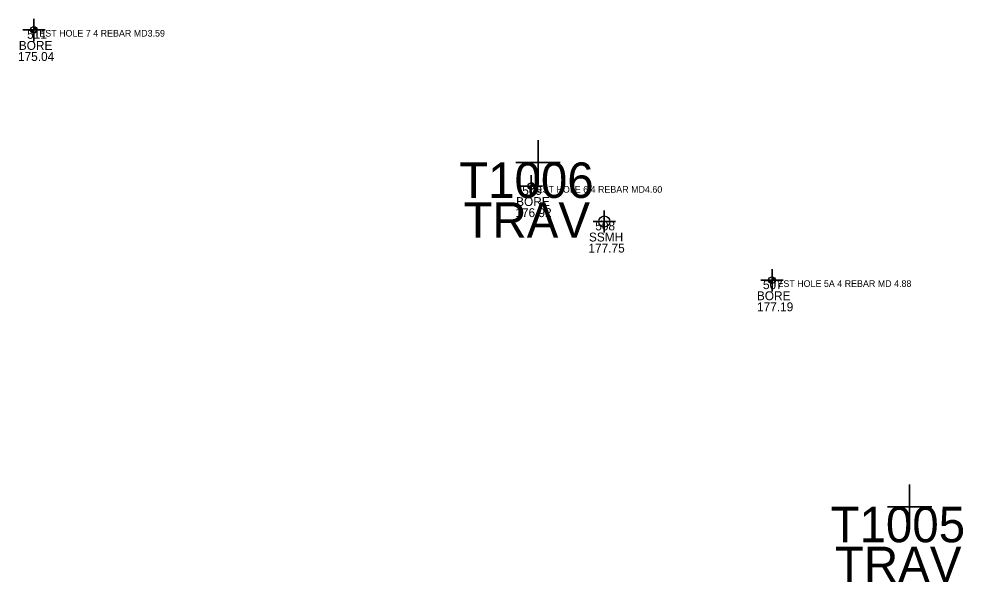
# Model space of a CAD drawing. Extents: x 1969314 to 1970910, y 795817 to 797766.
# Drawn here: x 1969314.1 to 1969527.1, y 797638.9 to 797766 of the extents above; entities that cross this region are included whole.
import ezdxf

# ---------------------------------------------------------------- set-up
doc = ezdxf.new("R2010")
doc.units = 0
for name, color, linetype in [('Level 63', 7, 'Continuous'), ('SV_Control_Boring', 7, 'Continuous'), ('SV_Control_Boring_Code', 7, 'Continuous'), ('SV_Control_Boring_Elev', 7, 'Continuous'), ('SV_Control_Boring_Name', 7, 'Continuous'), ('SV_Control_Boring_Shot', 7, 'Continuous'), ('SV_Control_CP_Code', 7, 'Continuous'), ('SV_Control_CP_Name', 7, 'Continuous'), ('SV_Control_CP_Shot', 7, 'Continuous'), ('SV_SS_Appurt_Code', 7, 'Continuous'), ('SV_SS_Appurt_Elev', 7, 'Continuous'), ('SV_SS_Appurt_name', 7, 'Continuous'), ('SV_SS_Appurtenances', 7, 'Continuous'), ('SV_SS_Appurtenances_Shots', 7, 'Continuous')]:
    doc.layers.add(name, color=color, linetype=linetype)

msp = doc.modelspace()

# ---------------------------------------------------------------- linework, layer by layer
at = {"layer": 'SV_Control_Boring'}
for p, q in [((1969316.79, 797763.55), (1969318.29, 797763.55)), ((1969317.54, 797762.8), (1969317.54, 797764.3)), ((1969429.7, 797727.55), (1969429.7, 797729.05)), ((1969428.95, 797728.3), (1969430.45, 797728.3)), ((1969483.99, 797706.29), (1969483.99, 797707.79)), ((1969483.24, 797707.04), (1969484.74, 797707.04))]:
    msp.add_line(p, q, dxfattribs=at)
for centre in [(1969317.54, 797763.55), (1969429.7, 797728.3), (1969483.99, 797707.04)]:
    msp.add_circle(centre, 0.75, dxfattribs=at)
for centre, radius, start, end in [((1969317.54, 797763.55), 0.698, 179.9999, 270.0002), ((1969317.54, 797763.55), 0.635, 179.9999, 270.0002), ((1969317.54, 797763.55), 0.573, 179.9999, 270.0002), ((1969317.54, 797763.55), 0.51, 179.9999, 270.0002), ((1969317.54, 797763.55), 0.448, 179.9999, 270.0002), ((1969317.54, 797763.55), 0.385, 179.9999, 270.0002), ((1969317.54, 797763.55), 0.693, 0.0001, 89.9995), ((1969317.54, 797763.55), 0.631, 0.0001, 89.9995), ((1969317.54, 797763.55), 0.569, 0.0001, 89.9995), ((1969317.54, 797763.55), 0.507, 0.0001, 89.9995), ((1969317.54, 797763.55), 0.445, 0.0001, 89.9995), ((1969317.54, 797763.55), 0.384, 0.0001, 89.9995), ((1969317.54, 797763.55), 0.322, 0.0001, 89.9995), ((1969429.7, 797728.3), 0.693, 0.0001, 89.9995), ((1969429.7, 797728.3), 0.631, 0.0001, 89.9995), ((1969429.7, 797728.3), 0.569, 0.0001, 89.9995), ((1969429.7, 797728.3), 0.507, 0.0001, 89.9995), ((1969429.7, 797728.3), 0.445, 0.0001, 89.9995), ((1969429.7, 797728.3), 0.384, 0.0001, 89.9995), ((1969429.7, 797728.3), 0.322, 0.0001, 89.9995), ((1969429.7, 797728.3), 0.698, 179.9999, 270.0002), ((1969429.7, 797728.3), 0.635, 179.9999, 270.0002), ((1969429.7, 797728.3), 0.573, 179.9999, 270.0002), ((1969429.7, 797728.3), 0.51, 179.9999, 270.0002), ((1969429.7, 797728.3), 0.448, 179.9999, 270.0002), ((1969429.7, 797728.3), 0.385, 179.9999, 270.0002), ((1969483.99, 797707.04), 0.693, 0.0001, 89.9995), ((1969483.99, 797707.04), 0.631, 0.0001, 89.9995), ((1969483.99, 797707.04), 0.569, 0.0001, 89.9995), ((1969483.99, 797707.04), 0.507, 0.0001, 89.9995), ((1969483.99, 797707.04), 0.445, 0.0001, 89.9995), ((1969483.99, 797707.04), 0.384, 0.0001, 89.9995), ((1969483.99, 797707.04), 0.322, 0.0001, 89.9995), ((1969483.99, 797707.04), 0.698, 179.9999, 270.0002), ((1969483.99, 797707.04), 0.635, 179.9999, 270.0002), ((1969483.99, 797707.04), 0.573, 179.9999, 270.0002), ((1969483.99, 797707.04), 0.51, 179.9999, 270.0002), ((1969483.99, 797707.04), 0.448, 179.9999, 270.0002), ((1969483.99, 797707.04), 0.385, 179.9999, 270.0002)]:
    msp.add_arc(centre, radius, start, end, dxfattribs=at)
at = {"layer": 'SV_Control_Boring_Shot'}
for points in [[(1969317.54, 797763.55), (1969317.54, 797766.05), (1969317.54, 797763.55), (1969315.04, 797763.55), (1969317.54, 797763.55), (1969317.54, 797761.05), (1969317.54, 797763.55), (1969320.04, 797763.55)], [(1969429.7, 797728.3), (1969429.7, 797730.8), (1969429.7, 797728.3), (1969427.2, 797728.3), (1969429.7, 797728.3), (1969429.7, 797725.8), (1969429.7, 797728.3), (1969432.2, 797728.3)], [(1969483.99, 797707.04), (1969483.99, 797709.54), (1969483.99, 797707.04), (1969481.49, 797707.04), (1969483.99, 797707.04), (1969483.99, 797704.54), (1969483.99, 797707.04), (1969486.49, 797707.04)]]:
    msp.add_lwpolyline(points, close=True, dxfattribs=at)
at = {"layer": 'SV_Control_CP_Shot'}
for points in [[(1969431.24, 797733.63), (1969431.24, 797738.63), (1969431.24, 797733.63), (1969426.24, 797733.63), (1969431.24, 797733.63), (1969431.24, 797728.63), (1969431.24, 797733.63), (1969436.24, 797733.63)], [(1969515, 797655.9), (1969515, 797660.9), (1969515, 797655.9), (1969510, 797655.9), (1969515, 797655.9), (1969515, 797650.9), (1969515, 797655.9), (1969520, 797655.9)]]:
    msp.add_lwpolyline(points, close=True, dxfattribs=at)
at = {"layer": 'SV_SS_Appurtenances'}
msp.add_circle((1969446.17, 797720.3), 1.25, dxfattribs=at)
at = {"layer": 'SV_SS_Appurtenances_Shots'}
msp.add_lwpolyline([(1969446.17, 797720.3), (1969446.17, 797722.8), (1969446.17, 797720.3), (1969443.67, 797720.3), (1969446.17, 797720.3), (1969446.17, 797717.8), (1969446.17, 797720.3), (1969448.67, 797720.3)], close=True, dxfattribs=at)

# ---------------------------------------------------------------- texts
at = {"layer": 'Level 63'}
for s, p in [('TEST HOLE 7 4 REBAR MD3.59', (1969317.54, 797762.05)), ('TEST HOLE 6 4 REBAR MD4.60', (1969429.7, 797726.8)), ('TEST HOLE 5A 4 REBAR MD 4.88', (1969483.99, 797705.54))]:
    msp.add_text(s, height=1.5, dxfattribs=at).set_placement(p)
at = {"layer": 'SV_Control_Boring_Code'}
for p in [(1969314.12, 797759.05), (1969426.28, 797723.8), (1969480.58, 797702.54)]:
    msp.add_text('BORE', height=2, dxfattribs=at).set_placement(p)
at = {"layer": 'SV_Control_Boring_Elev'}
for s, p in [('175.04', (1969313.94, 797756.55)), ('176.92', (1969426.11, 797721.3)), ('177.19', (1969480.6, 797700.04))]:
    msp.add_text(s, height=2, dxfattribs=at).set_placement(p)
at = {"layer": 'SV_Control_Boring_Name'}
for s, p in [('511', (1969316, 797761.55)), ('509', (1969427.66, 797726.3)), ('507', (1969481.95, 797705.04))]:
    msp.add_text(s, height=2, dxfattribs=at).set_placement(p)
at = {"layer": 'SV_Control_CP_Code'}
for p in [(1969414.42, 797716.63), (1969498.18, 797638.9)]:
    msp.add_text('TRAV', height=8, dxfattribs=at).set_placement(p)
at = {"layer": 'SV_Control_CP_Name'}
for s, p in [('T1006', (1969413.44, 797725.63)), ('T1005', (1969497.2, 797647.9))]:
    msp.add_text(s, height=8, dxfattribs=at).set_placement(p)
at = {"layer": 'SV_SS_Appurt_Code'}
msp.add_text('SSMH', height=2, dxfattribs=at).set_placement((1969442.7, 797715.8))
at = {"layer": 'SV_SS_Appurt_Elev'}
msp.add_text('177.75', height=2, dxfattribs=at).set_placement((1969442.59, 797713.3))
at = {"layer": 'SV_SS_Appurt_name'}
msp.add_text('508', height=2, dxfattribs=at).set_placement((1969444.13, 797718.3))
at = {"layer": 'SV_SS_Appurtenances'}
for s, rotation, p in [('M', 64.4229, (1969445.5, 797720.5)), ('A', 36.346, (1969445.65, 797720.78)), ('N', 17.6281, (1969445.88, 797720.94)), ('H', 358.9101, (1969446.14, 797721)), ('O', 330.8333, (1969446.41, 797720.97)), ('L', 312.1153, (1969446.65, 797720.81)), ('E', 293.3974, (1969446.79, 797720.62)), ('C', 319.2946, (1969445.49, 797719.71)), ('O', 338.0125, (1969445.75, 797719.5)), ('V', 6.0894, (1969446.14, 797719.4)), ('E', 24.8073, (1969446.47, 797719.45)), ('R', 43.5252, (1969446.75, 797719.61))]:
    msp.add_text(s, height=0.2, rotation=rotation, dxfattribs=at).set_placement(p)

doc.saveas('drawing.dxf')
